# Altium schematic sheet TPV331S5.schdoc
size 127 x 101 mm
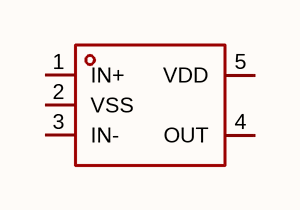
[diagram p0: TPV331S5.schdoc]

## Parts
U?  tpv331s5  [SOT-23-5_L3.0-W1.7-P0.95-LS2.8-BR]  (value not drawn)

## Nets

Not connected (* = marked no-connect by the designer): U? 1(IN+) 2(VSS) 3(IN-) 4(OUT) 5(VDD)

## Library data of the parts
U? = tpv331s5: Manufacturer: TECH PUBLIC(台舟); AddInBom: yes; ModelId: 0a2a1b8f50944f73965918ad6e5fe167; ModelName: SOT-23-5_L2.9-W1.6-H1.1-LS2.8-P0.95; ModelTransform: 114.173,109.636,0,180,0,0,0,0,0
